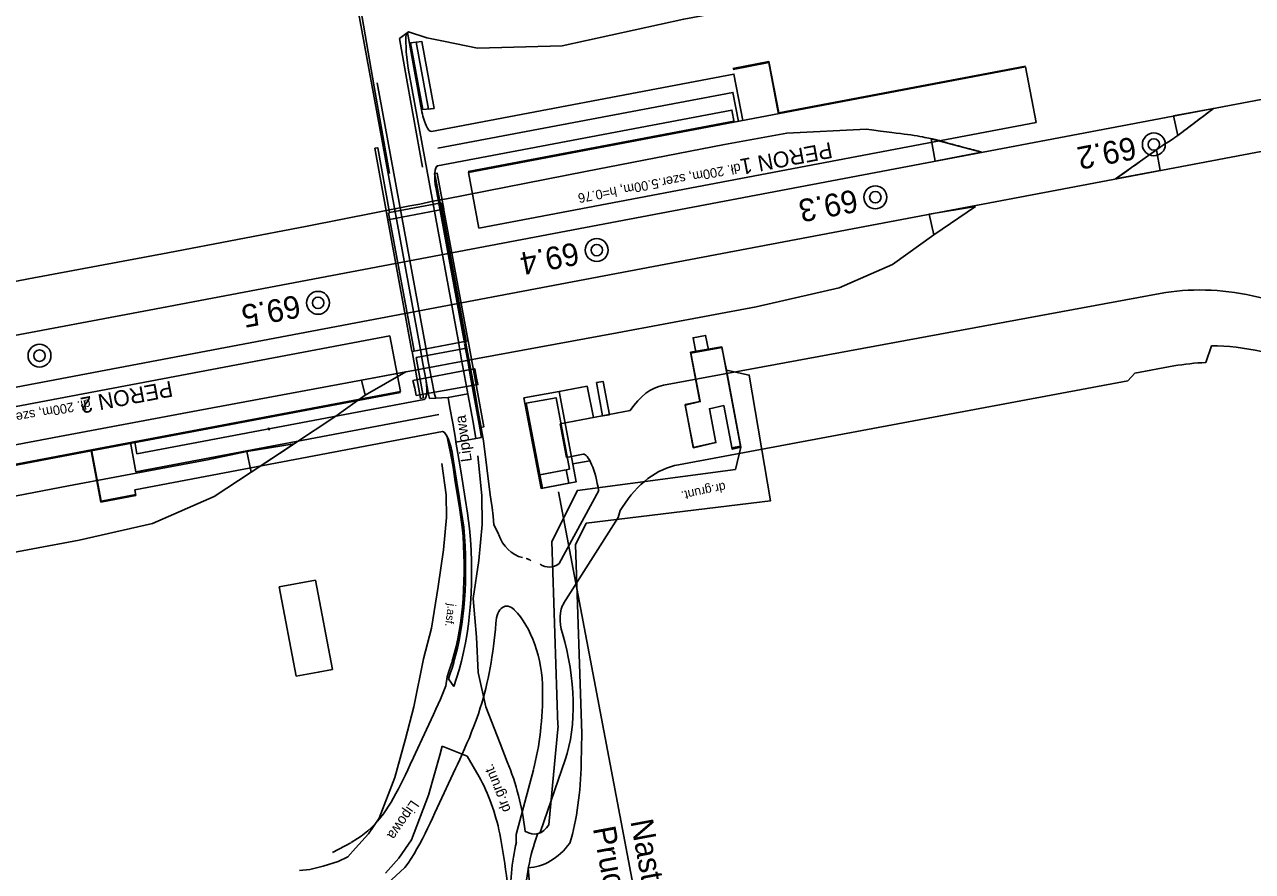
# Model space of a CAD drawing. Extents: x 6541740 to 6556805, y 5525233 to 5530361.
# Drawn here: x 6555210.5 to 6555318.7, y 5525741.4 to 5525816.1 of the extents above; entities that cross this region are included whole.
import ezdxf

# ---------------------------------------------------------------- set-up
doc = ezdxf.new("R2010")
doc.units = 0
for name, color, linetype in [('Default', 7, 'Continuous'), ('TOR_SCH-budynki', 7, 'Continuous'), ('TOR_SCH-hektometry', 7, 'Continuous'), ('TOR_SCH-obiekty projektowane', 7, 'Continuous'), ('TOR_SCH-perony', 7, 'Continuous'), ('TOR_SCH-przejazdy+drogi istniejace', 7, 'Continuous'), ('TOR_SCH-przejazdy+drogi projektowane', 7, 'Continuous'), ('TOR_SCH-tory i rozjazdy do rozbiorki', 7, 'Continuous'), ('TOR_SCH-tory projektowane', 7, 'Continuous')]:
    doc.layers.add(name, color=color, linetype=linetype)

# ---------------------------------------------------------------- blocks, each defined once
blk = doc.blocks.new('4010_1')
at = {"layer": 'Default'}
for radius in [0.75, 0.375]:
    blk.add_circle((0, 0), radius, dxfattribs=at)

msp = doc.modelspace()

# ---------------------------------------------------------------- linework, layer by layer
at = {"layer": 'TOR_SCH-budynki'}
for p, q in [((6555269.19, 5525787.23), (6555271.94, 5525787.72)), ((6555269.64, 5525787.23), (6555269.4, 5525788.5)), ((6555271.94, 5525787.72), (6555273.59, 5525778.94)), ((6555270, 5525782.87), (6555269.19, 5525787.23)), ((6555268.7, 5525782.61), (6555270, 5525782.87)), ((6555269.42, 5525778.84), (6555268.7, 5525782.61)), ((6555269.43, 5525778.8), (6555268.71, 5525782.57)), ((6555271.38, 5525779.28), (6555269.42, 5525778.84)), ((6555273.59, 5525778.94), (6555272.81, 5525778.81)), ((6555236.12, 5525767.14), (6555232.91, 5525766.55)), ((6555236.12, 5525767.14), (6555237.61, 5525759.25)), ((6555232.91, 5525766.55), (6555234.41, 5525758.66))]:
    msp.add_line(p, q, dxfattribs=at)
msp.add_lwpolyline([(6555269.64, 5525787.23), (6555269.4, 5525788.5), (6555270.51, 5525788.71), (6555270.75, 5525787.44)], close=True, dxfattribs=at)
for points in [[(6555269.21, 5525787.15), (6555271.94, 5525787.66), (6555272.34, 5525785.65), (6555273.6, 5525778.86)], [(6555268.71, 5525782.57), (6555270.03, 5525782.87), (6555269.21, 5525787.15)], [(6555269.43, 5525778.8), (6555271.41, 5525779.26), (6555270.84, 5525782.24), (6555272.11, 5525782.53), (6555272.85, 5525778.68), (6555273.6, 5525778.86)], [(6555237.61, 5525759.25), (6555236.36, 5525759), (6555234.41, 5525758.66)]]:
    msp.add_lwpolyline(points, dxfattribs=at)
at = {"layer": 'TOR_SCH-obiekty projektowane'}
for p, q in [((6555244.8, 5525787.34), (6555242.56, 5525799.53)), ((6555249.39, 5525788.2), (6555247.15, 5525800.4)), ((6555249.57, 5525788.22), (6555247.32, 5525800.41)), ((6555244.62, 5525787.32), (6555242.38, 5525799.52)), ((6555260.06, 5525784.23), (6555257.6, 5525783.78)), ((6555260.61, 5525781.46), (6555260.06, 5525784.23)), ((6555217.2, 5525774.01), (6555216.34, 5525778.53)), ((6555217.21, 5525774.09), (6555216.35, 5525778.61)), ((6555260.3, 5525777.66), (6555258.81, 5525777.39)), ((6555220.26, 5525774.67), (6555217.21, 5525774.09)), ((6555257.53, 5525774.92), (6555267.23, 5525723.78)), ((6555220.28, 5525774.59), (6555217.2, 5525774.01))]:
    msp.add_line(p, q, dxfattribs=at)
for points in [[(6555246.58, 5525808.73), (6555245.59, 5525808.63), (6555244.5, 5525814.53), (6555245.5, 5525814.63)], [(6555246.58, 5525808.73), (6555246.09, 5525808.68), (6555245, 5525814.58), (6555245.5, 5525814.63)], [(6555260.88, 5525784.55), (6555261.47, 5525784.66), (6555262.02, 5525781.72), (6555261.43, 5525781.61)], [(6555254.49, 5525783.2), (6555257.6, 5525783.78), (6555259.11, 5525775.8), (6555256, 5525775.22)], [(6555258.52, 5525776.91), (6555255.9, 5525776.42), (6555254.7, 5525782.73), (6555257.33, 5525783.22)], [(6555255.9, 5525776.42), (6555258.21, 5525776.85), (6555258.44, 5525775.67), (6555256.12, 5525775.24)]]:
    msp.add_lwpolyline(points, close=True, dxfattribs=at)
for points in [[(6555276.95, 5525808.34), (6555276.09, 5525812.86), (6555272.91, 5525812.26)], [(6555276.83, 5525808.83), (6555276.09, 5525812.78), (6555272.93, 5525812.18)], [(6555273.79, 5525807.66), (6555273.01, 5525811.76), (6555246.33, 5525806.7)], [(6555246.89, 5525805.24), (6555272.92, 5525810.15), (6555273.4, 5525807.59)], [(6555273.02, 5525807.52), (6555272.82, 5525808.58), (6555246.87, 5525803.66)], [(6555276.94, 5525808.26), (6555276.83, 5525808.83)], [(6555247.06, 5525800.38), (6555242.64, 5525799.55), (6555241.6, 5525805.27), (6555241.35, 5525805.22), (6555242.49, 5525798.91), (6555247.43, 5525799.84), (6555246.85, 5525803.01), (6555246.6, 5525802.97), (6555246.6, 5525802.97), (6555247.06, 5525800.38)], [(6555245.64, 5525783.2), (6555245.64, 5525783.2), (6555245, 5525786.76), (6555249.42, 5525787.6), (6555250.68, 5525780.59), (6555250.94, 5525780.64), (6555249.56, 5525788.24), (6555244.63, 5525787.3), (6555245.38, 5525783.15), (6555245.64, 5525783.2)], [(6555245.69, 5525783.07), (6555220.37, 5525778.27), (6555220.17, 5525779.33)], [(6555247, 5525781.75), (6555220.28, 5525776.68), (6555219.79, 5525779.26)], [(6555247.3, 5525780.23), (6555220.18, 5525775.09), (6555220.28, 5525774.59)]]:
    msp.add_lwpolyline(points, dxfattribs=at)
for centre, major_axis, start_param, end_param in [((6555245.96, 5525808.67), (0.37, -1.97), 4.690058, 6.283185), ((6555247.24, 5525801.7), (-0.37, 1.97), 6.283185, 7.831651), ((6555245.31, 5525785.03), (-0.37, 1.97), 3.141593, 4.686711), ((6555247.67, 5525778.26), (-0.37, 1.97), 4.640081, 6.283185)]:
    msp.add_ellipse(centre, major_axis=major_axis, ratio=0.25, start_param=start_param, end_param=end_param, dxfattribs=at)
msp.add_ellipse((6555232, 5525780.47), major_axis=(-0.0186, 0.0983), ratio=0.25, dxfattribs=at)
at = {"layer": 'TOR_SCH-perony'}
for p, q in [((6555298.72, 5525812.39), (6555249.59, 5525803.08)), ((6555298.7, 5525812.47), (6555276.95, 5525808.34)), ((6555298.72, 5525812.39), (6555299.65, 5525807.48)), ((6555273.01, 5525807.6), (6555249.58, 5525803.16)), ((6555299.65, 5525807.48), (6555250.52, 5525798.16)), ((6555249.59, 5525803.08), (6555250.52, 5525798.16)), ((6555242.67, 5525788.69), (6555193.54, 5525779.37)), ((6555242.67, 5525788.69), (6555243.6, 5525783.77)), ((6555243.62, 5525783.69), (6555216.34, 5525778.53)), ((6555243.6, 5525783.77), (6555216.35, 5525778.61)), ((6555216.35, 5525778.61), (6555194.48, 5525774.46)), ((6555216.34, 5525778.53), (6555194.49, 5525774.38))]:
    msp.add_line(p, q, dxfattribs=at)
at = {"layer": 'TOR_SCH-przejazdy+drogi istniejace'}
for p, q in [((6555257.51, 5525754.28), (6555257.28, 5525751.84)), ((6555259.55, 5525751.02), (6555259.6, 5525753.59)), ((6555256.69, 5525745.56), (6555257.28, 5525751.84)), ((6555255.62, 5525732.67), (6555254.85, 5525741.75))]:
    msp.add_line(p, q, dxfattribs=at)
for points in [[(6555242.64, 5525802.98), (6555241.29, 5525810.65), (6555239.54, 5525820.69), (6555236.84, 5525835.55), (6555235.45, 5525843.55)], [(6555245.93, 5525814.97), (6555247.4, 5525814.66), (6555250.39, 5525814.05), (6555257.86, 5525814.24), (6555268.58, 5525816.61), (6555283.95, 5525819.5), (6555297.12, 5525822.42), (6555318.23, 5525825.3), (6555325.99, 5525826.63)], [(6555243.52, 5525814.89), (6555244.3, 5525815.48), (6555245.93, 5525814.97)], [(6555245.55, 5525803.54), (6555244.21, 5525810.91), (6555243.52, 5525814.89)], [(6555272.34, 5525785.65), (6555274.36, 5525785.21), (6555276.24, 5525774.13), (6555259.98, 5525772.15)], [(6555250.32, 5525762.1), (6555250.01, 5525765.52), (6555250.51, 5525768.85), (6555250.82, 5525772.05), (6555250.77, 5525774.58), (6555250.42, 5525778.08)], [(6555259.2, 5525775.04), (6555273.14, 5525776.89), (6555273.6, 5525778.86)], [(6555239.65, 5525743.48), (6555240.78, 5525744.75), (6555241.73, 5525746.14), (6555243.11, 5525749.73), (6555244.05, 5525753.13), (6555244.78, 5525755.94), (6555245.63, 5525760.19), (6555246.35, 5525762.88), (6555246.92, 5525766.58), (6555247.4, 5525769.8), (6555247.67, 5525772.64), (6555247.63, 5525774.66), (6555247.24, 5525777.41)], [(6555273.14, 5525776.89), (6555259.2, 5525775.04), (6555256.94, 5525770.53), (6555257.49, 5525754.3)], [(6555259.6, 5525753.59), (6555259.05, 5525770.25), (6555259.98, 5525772.15), (6555276.24, 5525774.13)], [(6555250.32, 5525762.1), (6555250.45, 5525758.97), (6555251.14, 5525755.95), (6555252.39, 5525752.72), (6555253.01, 5525751.1)], [(6555242.29, 5525741.28), (6555243.47, 5525742.6), (6555244.58, 5525744.23), (6555246.09, 5525748.15), (6555247.07, 5525751.7), (6555247.27, 5525752.48)], [(6555250.55, 5525749.79), (6555249.48, 5525751.59), (6555247.27, 5525752.48)], [(6555239.65, 5525743.48), (6555238.96, 5525742.73), (6555238.1, 5525742.3), (6555236.78, 5525741.89), (6555235.6, 5525741.6), (6555234.69, 5525741.52)]]:
    msp.add_lwpolyline(points, dxfattribs=at)
msp.add_lwpolyline([(6555249.96, 5525785.74), (6555249.59, 5525785.67), (6555244.7, 5525784.73), (6555244.87, 5525784.06), (6555245, 5525783.42), (6555249.93, 5525784.29), (6555250.43, 5525784.38), (6555250.32, 5525784.93), (6555250.16, 5525785.78)], close=True, dxfattribs=at)
for centre, major_axis, start_param, end_param in [((6555248.61, 5525745.6), (-2.18, 11.45), 4.564417, 5.116223), ((6555248.54, 5525757.26), (-3.92, 20.59), 3.916546, 4.310739), ((6555247.39, 5525743.45), (-1.92, 10.08), 4.747485, 5.293863), ((6555254.74, 5525749.54), (-0.91, 4.79), 2.71727, 3.641992), ((6555231.38, 5525741.24), (-7.96, 41.78), 4.50108, 4.701549), ((6555252.23, 5525758.51), (-3.18, 16.69), 3.075126, 3.562422)]:
    msp.add_ellipse(centre, major_axis=major_axis, ratio=0.499999, start_param=start_param, end_param=end_param, dxfattribs=at)
at = {"layer": 'TOR_SCH-przejazdy+drogi projektowane'}
for p, q in [((6555244.22, 5525815.42), (6555245.46, 5525808.62)), ((6555244.37, 5525811.8), (6555248.74, 5525788.01)), ((6555241.55, 5525811), (6555245.84, 5525787.66)), ((6555246.66, 5525802.8), (6555249.36, 5525788.07)), ((6555246.75, 5525801.63), (6555249.24, 5525788.06)), ((6555266.79, 5525784.32), (6555310.58, 5525792.41)), ((6555318.72, 5525792.2), (6555326.91, 5525790.39)), ((6555315.11, 5525787.8), (6555314.62, 5525786.32)), ((6555308.35, 5525785.38), (6555311.79, 5525786.02)), ((6555268.12, 5525777.3), (6555307.72, 5525784.7)), ((6555307.72, 5525784.7), (6555308.35, 5525785.38)), ((6555247.81, 5525783.23), (6555249.55, 5525783.55)), ((6555246.15, 5525783.16), (6555247.81, 5525783.23)), ((6555263.87, 5525782.08), (6555257.69, 5525780.9)), ((6555257.69, 5525780.9), (6555258.25, 5525777.94)), ((6555248.5, 5525779.29), (6555250.25, 5525779.61)), ((6555250.25, 5525779.61), (6555250.74, 5525779.7)), ((6555259.71, 5525778.23), (6555258.25, 5525777.95)), ((6555257.99, 5525765.08), (6555262.81, 5525772.65)), ((6555262.81, 5525772.65), (6555262.98, 5525773.27)), ((6555262.98, 5525773.27), (6555263.15, 5525773.53)), ((6555247.72, 5525758.6), (6555247.61, 5525757.8)), ((6555247.84, 5525758.43), (6555248.3, 5525757.75)), ((6555246.11, 5525754.4), (6555244.55, 5525751.04)), ((6555255.96, 5525744.97), (6555258.13, 5525751.28)), ((6555255.32, 5525750.41), (6555253.82, 5525744.7)), ((6555239.27, 5525743.98), (6555239.82, 5525744.35)), ((6555253.82, 5525744.7), (6555253.82, 5525744.03)), ((6555255.43, 5525743.94), (6555255.7, 5525744.71)), ((6555255.7, 5525744.71), (6555255.96, 5525744.97)), ((6555239.22, 5525743.95), (6555237.62, 5525743.11)), ((6555244, 5525741.78), (6555242.44, 5525740.33))]:
    msp.add_line(p, q, dxfattribs=at)
for points in [[(6555232.86, 5525855.52), (6555232.99, 5525854.81), (6555233.25, 5525853.4), (6555233.51, 5525852), (6555233.51, 5525852), (6555241.02, 5525811.14), (6555245.34, 5525787.61)], [(6555245.84, 5525787.66), (6555246.09, 5525786.27), (6555246.35, 5525784.89), (6555246.6, 5525783.52), (6555246.72, 5525783.18)], [(6555248.75, 5525787.96), (6555249, 5525786.57), (6555249.26, 5525785.16), (6555249.52, 5525783.75), (6555249.55, 5525783.55)], [(6555249.25, 5525788.01), (6555249.5, 5525786.61), (6555249.76, 5525785.2), (6555250.02, 5525783.77), (6555250.28, 5525782.34), (6555250.54, 5525780.88), (6555250.74, 5525779.7)], [(6555249.37, 5525788.02), (6555249.63, 5525786.62), (6555249.89, 5525785.21), (6555250.15, 5525783.78), (6555250.41, 5525782.34), (6555250.67, 5525780.88), (6555250.92, 5525779.41)], [(6555245.34, 5525787.61), (6555245.59, 5525786.23), (6555245.85, 5525784.85), (6555246.09, 5525783.49), (6555246.15, 5525783.16)], [(6555249.55, 5525783.55), (6555249.77, 5525782.32), (6555250.03, 5525780.89), (6555250.25, 5525779.61)], [(6555247.81, 5525783.23), (6555247.97, 5525782.33), (6555248.21, 5525780.98), (6555248.45, 5525779.63), (6555248.5, 5525779.29)], [(6555247.73, 5525779.77), (6555248.13, 5525777.73), (6555248.24, 5525777.08), (6555248.44, 5525775.81), (6555248.64, 5525774.56), (6555248.83, 5525773.32), (6555249.05, 5525771.81)], [(6555248.5, 5525779.29), (6555248.67, 5525778.29), (6555248.9, 5525776.96), (6555249.11, 5525775.64), (6555249.31, 5525774.33), (6555249.51, 5525773.03), (6555249.7, 5525771.69)], [(6555252.27, 5525771.14), (6555251.85, 5525772.01), (6555251.77, 5525772.77), (6555251.68, 5525773.53), (6555251.58, 5525774.28), (6555251.52, 5525774.65), (6555250.92, 5525779.41)], [(6555248.12, 5525778.55), (6555248.37, 5525777.06), (6555248.58, 5525775.78), (6555248.78, 5525774.51), (6555248.96, 5525773.26), (6555249.18, 5525771.79)], [(6555261.08, 5525775.03), (6555257.6, 5525768.59)], [(6555248.18, 5525760.02), (6555248.03, 5525759.52), (6555247.88, 5525759.06), (6555247.72, 5525758.6)], [(6555248.3, 5525759.86), (6555248.15, 5525759.36), (6555248, 5525758.89), (6555247.84, 5525758.43)], [(6555247.61, 5525757.8), (6555247.31, 5525757.07), (6555247.12, 5525756.63), (6555246.93, 5525756.18), (6555246.73, 5525755.74), (6555246.53, 5525755.29), (6555246.32, 5525754.85), (6555246.11, 5525754.4)], [(6555244, 5525741.78), (6555244.27, 5525742.16), (6555244.54, 5525742.57), (6555244.8, 5525743), (6555245.05, 5525743.43), (6555245.3, 5525743.87), (6555245.54, 5525744.32), (6555245.77, 5525744.77), (6555245.99, 5525745.23), (6555246.21, 5525745.69), (6555246.43, 5525746.14), (6555246.64, 5525746.6), (6555246.85, 5525747.05), (6555246.85, 5525747.05), (6555248.46, 5525750.52), (6555248.41, 5525750.41), (6555248.62, 5525750.86), (6555248.84, 5525751.32), (6555249.05, 5525751.78), (6555249.26, 5525752.26), (6555249.47, 5525752.74), (6555249.68, 5525753.23), (6555249.88, 5525753.74), (6555250.08, 5525754.25), (6555250.28, 5525754.78), (6555250.47, 5525755.33), (6555250.64, 5525755.86)], [(6555244.68, 5525751.31), (6555244.47, 5525750.86), (6555244.26, 5525750.41), (6555244.05, 5525749.97), (6555243.84, 5525749.54), (6555243.64, 5525749.12), (6555243.43, 5525748.71), (6555243.21, 5525748.32), (6555243, 5525747.93), (6555242.78, 5525747.56), (6555242.56, 5525747.2), (6555242.34, 5525746.86), (6555242.1, 5525746.51)]]:
    msp.add_lwpolyline(points, dxfattribs=at)
for centre, major_axis, ratio, start_param, end_param in [((6555245.62, 5525811.92), (-0.93, 4.91), 0.25, 0.758321, 1.548465), ((6555245.96, 5525808.67), (0.37, -1.97), 0.25, 4.690058, 6.279955), ((6555247.24, 5525801.68), (-0.37, 1.97), 0.25, 6.279955, 7.831651), ((6555366.83, 5525495.18), (-56.34, 297.21), 0.25, 6.176516, 6.281998), ((6555366.83, 5525495.18), (-55.41, 292.3), 0.25, 6.176516, 6.233631), ((6555366.83, 5525495.18), (-55.13, 290.82), 0.25, 6.243667, 6.281998), ((6555276.55, 5525732.74), (-9.78, 51.58), 0.25, 6.281998, 6.535305), ((6555247.67, 5525778.26), (-0.37, 1.97), 0.25, 4.81114, 6.283185), ((6555260.27, 5525775.28), (-0.56, 2.95), 0.25, 4.578281, 6.283592), ((6555272.54, 5525753.97), (-4.44, 23.33), 0.499999, 6.281393, 6.771299), ((6555237.67, 5525773.93), (-4.11, 21.59), 0.499999, 3.919278, 4.519453), ((6555237.67, 5525773.93), (-4.16, 21.83), 0.499999, 3.919278, 4.519453), ((6555237.67, 5525773.93), (-4.35, 22.81), 0.499999, 3.83349, 4.519453), ((6555254.88, 5525772.13), (-0.58, 3.05), 0.897189, 1.728216, 2.750899), ((6555254.48, 5525767.93), (-0.21, 1.1), 0.976601, 5.483546, 5.892492), ((6555256.72, 5525769.68), (-0.26, 1.38), 0.999987, 2.341953, 3.629706), ((6555253.32, 5525762.37), (-0.47, 2.46), 0.499999, 5.655689, 7.358003), ((6555258.93, 5525763.12), (-0.44, 2.33), 0.499999, 0.488113, 1.775866), ((6555252.79, 5525759.07), (-1.19, 6.26), 0.499999, 4.357266, 5.655689), ((6555237.67, 5525773.93), (-5.15, 27.04), 0.499999, 3.889479, 4.21641), ((6555252.79, 5525759.07), (-2.15, 11.3), 0.499999, 3.861049, 4.917459), ((6555245.76, 5525762.47), (-3.7, 19.4), 0.499999, 3.950241, 4.357266), ((6555233.72, 5525765.42), (-4.16, 21.83), 0.499999, 3.327431, 3.579278), ((6555261.82, 5525734.62), (-3.04, 15.96), 0.499999, 0.849414, 1.244004), ((6555261.82, 5525734.62), (-2.57, 13.51), 0.499999, 0.719457, 1.244004)]:
    msp.add_ellipse(centre, major_axis=major_axis, ratio=ratio, start_param=start_param, end_param=end_param, dxfattribs=at)
at = {"layer": 'TOR_SCH-tory i rozjazdy do rozbiorki'}
for p, q in [((6555223.1, 5525796), (6555235.39, 5525798.36)), ((6555225.78, 5525782.1), (6555238.12, 5525784.38)), ((6555238.12, 5525784.38), (6555240.17, 5525784.76)), ((6555230.06, 5525778.47), (6555234.23, 5525779.15))]:
    msp.add_line(p, q, dxfattribs=at)
for points in [[(6555315.3, 5525808.74), (6555311.75, 5525808.07), (6555312.14, 5525806.35)], [(6555294.82, 5525804.88), (6555290.75, 5525804.08), (6555290.4, 5525806.06)], [(6555306.66, 5525802.52), (6555310.59, 5525803.26), (6555310.25, 5525805.07)], [(6555294.31, 5525800.08), (6555290.21, 5525799.4), (6555290.63, 5525797.58)], [(6555244.08, 5525785.49), (6555240.17, 5525784.76), (6555240.48, 5525783.43)], [(6555234.23, 5525779.15), (6555230.44, 5525776.64), (6555230.06, 5525778.47)]]:
    msp.add_lwpolyline(points, close=True, dxfattribs=at)
for points in [[(6555259.91, 5525803.17), (6555272.18, 5525805.55), (6555277.67, 5525806.54), (6555284.68, 5525806.91)], [(6555235.39, 5525798.36), (6555244.42, 5525800.13), (6555245.32, 5525800.3), (6555246.46, 5525800.54), (6555247.67, 5525800.77), (6555259.91, 5525803.17)], [(6555286.98, 5525794.96), (6555290.63, 5525797.58)], [(6555186.25, 5525789), (6555198.53, 5525791.32), (6555210.81, 5525793.69), (6555223.1, 5525796)], [(6555274.96, 5525791.23), (6555282.27, 5525792.91), (6555286.98, 5525794.96)], [(6555248.33, 5525786.3), (6555249.17, 5525786.45), (6555250.41, 5525786.68), (6555262.7, 5525788.95), (6555274.96, 5525791.23)], [(6555240.17, 5525784.76), (6555247.11, 5525786.06), (6555248.33, 5525786.3)], [(6555238.56, 5525782.05), (6555240.48, 5525783.43)], [(6555201.23, 5525777.46), (6555213.53, 5525779.81), (6555225.78, 5525782.1)], [(6555237.91, 5525781.58), (6555237.9, 5525781.58), (6555230.44, 5525776.64)], [(6555238.56, 5525782.05), (6555237.91, 5525781.58)], [(6555226.59, 5525777.74), (6555230.06, 5525778.47)], [(6555189.79, 5525770.76), (6555202.07, 5525773.1), (6555214.35, 5525775.45), (6555226.59, 5525777.73)], [(6555230.44, 5525776.64), (6555227.19, 5525774.5)], [(6555227.19, 5525774.5), (6555221.73, 5525772.13), (6555215.27, 5525770.65)], [(6555215.27, 5525770.65), (6555202.98, 5525768.35), (6555190.7, 5525766.04)]]:
    msp.add_lwpolyline(points, dxfattribs=at)
for points in [[(6555306.66, 5525802.52), (6555307.85, 5525803.36), (6555309.17, 5525804.31), (6555310.5, 5525805.26), (6555311.04, 5525805.64), (6555311.6, 5525805.95), (6555312.14, 5525806.35), (6555313.35, 5525807.27), (6555314.56, 5525808.18), (6555315.3, 5525808.74)], [(6555284.68, 5525806.91), (6555286.58, 5525806.63), (6555288.47, 5525806.46), (6555290.4, 5525806.06), (6555291.13, 5525805.91), (6555291.87, 5525805.67), (6555292.61, 5525805.47), (6555293.35, 5525805.28), (6555294.09, 5525805.08), (6555294.82, 5525804.88)]]:
    msp.add_open_spline(points, degree=3, dxfattribs=at)
at = {"layer": 'TOR_SCH-tory projektowane'}
for p, q in [((6555381.82, 5525821.35), (6555221.45, 5525790.95)), ((6555362.21, 5525813.05), (6555222.13, 5525786.49)), ((6555221.45, 5525790.95), (6555010.48, 5525750.96)), ((6555222.13, 5525786.49), (6554997.05, 5525743.82))]:
    msp.add_line(p, q, dxfattribs=at)

# ---------------------------------------------------------------- block references
at = {"layer": 'TOR_SCH-hektometry', "xscale": 1.345963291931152, "yscale": 1.345963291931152}
for p in [(6555310.03, 5525805.56), (6555285.47, 5525800.9), (6555260.91, 5525796.24), (6555236.34, 5525791.59), (6555211.78, 5525786.93)]:
    msp.add_blockref('4010_1', p, dxfattribs=at)

# ---------------------------------------------------------------- texts
at = {"layer": 'TOR_SCH-hektometry'}
for s, p in [('69.2', (6555308.25, 5525806.26)), ('69.3', (6555283.7, 5525801.61)), ('69.4', (6555259.13, 5525796.95)), ('69.5', (6555234.57, 5525792.3))]:
    msp.add_text(s, height=2, rotation=190.7691, dxfattribs=at).set_placement(p)
at = {"layer": 'TOR_SCH-obiekty projektowane'}
for s, p in [('Pruchna - BUDOWA', (6555260.56, 5525745.25)), ('Nastawnia Sterowania Miejscowego', (6555263.87, 5525745.87))]:
    msp.add_text(s, height=2, rotation=280.5213, dxfattribs=at).set_placement(p)
at = {"layer": 'TOR_SCH-perony'}
for s, height, rotation, p in [('PERON 1', 1.4, 190.7101, (6555281.53, 5525805.77)), ('dł. 200m, szer.5.00m, h=0.76', 0.84, 190.7075, (6555273.52, 5525803.91)), ('PERON 2', 1.4, 190.7101, (6555223.37, 5525784.72)), ('dł. 200m, szer.5.00m, h=0.76', 0.84, 190.7075, (6555216.2, 5525783.1))]:
    msp.add_text(s, height=height, rotation=rotation, dxfattribs=at).set_placement(p)
at = {"layer": 'TOR_SCH-przejazdy+drogi istniejace'}
for s, height, rotation, p in [('Lipowa', 0.979, 97.6671, (6555249.9, 5525777.62)), ('dr.grunt.', 0.8, 191.9668, (6555272.19, 5525775.76)), ('j.asf.', 0.72, 262.8972, (6555247.79, 5525765.09)), ('dr.grunt.', 0.897, 111.7391, (6555253.35, 5525746.86)), ('Lipowa', 0.908, 235.4751, (6555244.57, 5525747.8))]:
    msp.add_text(s, height=height, rotation=rotation, dxfattribs=at).set_placement(p)

doc.saveas('drawing.dxf')
